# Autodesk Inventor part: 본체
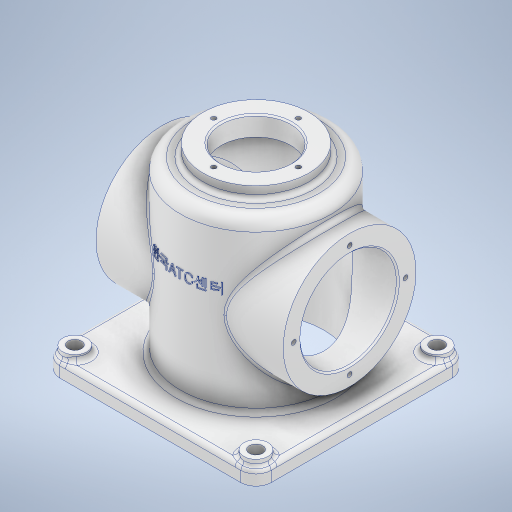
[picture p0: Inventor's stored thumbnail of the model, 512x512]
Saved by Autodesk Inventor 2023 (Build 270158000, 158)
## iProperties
Created: 2025-05
Part Number: 본체
Material: 알루미늄 6061
Document SubType Name: Modeling
Designer: ADMIN_PC
Mass: 1130.88 g
Surface Area: 1201.4 cm^2
Volume: 418.845 cm^3
Density: 2.7 g/cm^3
Appearance: 알루미늄 - 평지
Author: ADMIN_PC
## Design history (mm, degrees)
sketch "스케치1"
  geometry: L1 (-70, 70)-(70, 70); L2 (70, 70)-(70, -70); L3 (70, -70)-(-70, -70); L4 (-70, -70)-(-70, 70); L5 (-70, 70)-(70, -70); L6 (70, 70)-(-70, -70); 1 further point
  constraints: 12 end point, 2 midpoint, 2 parallel, 1 horizontal, 1 perpendicular
  dimensions: "d0" = 140 distance of L2.end L3.end; "d1" = 140 distance of L1.end L2.end
extrude "돌출1" new body sketch "스케치1" distance "d2" = 10; taper "d3" = 0 deg
sketch "스케치2"
  geometry: C1 r 50 at (0, 0); 1 further point
  constraints: 1 centre point, 1 coincident
  dimensions: "d4" = 100 diameter of C1
extrude "돌출2" join sketch "스케치2" distance "d5" = 112; taper "d6" = 0 deg
sketch "스케치3"
  geometry: C1 r 35 at (0, 0); 1 further point
  constraints: 1 centre point, 1 coincident
  dimensions: "d7" = 70 diameter of C1
extrude "돌출3" join sketch "스케치3" distance "d8" = 8; taper "d9" = 0 deg
node "작업 평면1"
sketch "스케치5"
  geometry: L1 (-26, 0)-(156, 0) reference; L2 (0, 0)-(65, 0); C1 r 44 at (65, 0)
  constraints: 2 end point, 1 centre point, 1 coincident, 1 midpoint
  dimensions: "d11" = 65 distance of L2.start L2.end; "d12" = 88 diameter of C1
extrude "돌출4" join sketch "스케치5" stored distance "d13" = 8; taper "d14" = 0 deg
sketch "스케치6" dims "d15" = 74
  geometry: L1 (0, -91)-(0, 91) reference; C1 r 44 at (0, 0) reference; 3 further points
  constraints: 1 coincident, 1 point on line, 1 vertical alignment, 2 other
hole "구멍1" sketch "스케치6" at (0, 37) diameter "d16" = 3.242; stored, may be unused: countersink angle "d20" = 90 deg, drill point angle "d22" = 118 deg; dims "d17" = 8, "d18" = 4, "d19" = 2, "d21" = 10
sketch "스케치7"
  geometry: C1 r 44 at (0, 0) reference; C2 r 32 at (0, 0); 1 further point
  constraints: 1 centre point, 1 coincident
  dimensions: "d26" = 64 diameter of C2
extrude "돌출5" cut sketch "스케치7" stored distance "d27" = 10; taper "d28" = 0 deg
sketch "스케치8"
  geometry: L1 (50, 10)-(50, 122) reference; L2 (-50, 10)-(-50, 122) reference; L3 (50, 122)-(-50, 122) reference; L4 (35, 130)-(-35, 130) reference; L5 (-35, 122)-(-35, 130) reference; L6 (35, 122)-(35, 130) reference; L7 (-35, 122)-(35, 122) reference; L8 (-70, 0)-(-70, 10) reference; L9 (70, 0)-(70, 10) reference; L10 (45, 10)-(45, 117); L11 (45, 0)-(45, 10); L12 (0, 117)-(0, 0); L13 (70, 0)-(-70, 0) reference; L14 (45, 0)-(0, 0); L15 (0, 117)-(45, 117)
  constraints: 10 end point, 3 perpendicular, 1 parallel
  dimensions: "d29" = 5 distance between parallel lines of L1 L10; "d30" = 117 distance of L12.start L12.end
revolve "회전1" sketch "스케치8" stored, may be unused: angle "d31" = 90 deg
sketch "스케치9" dims "d32" = 56
  geometry: L1 (0, 98)-(0, -98) reference; 3 further points
  constraints: 1 coincident, 1 point on line, 1 vertical alignment, 2 other
hole "구멍2" sketch "스케치9" at (0, 28) diameter "d33" = 3.242; stored, may be unused: countersink angle "d37" = 90 deg, drill point angle "d39" = 118 deg; dims "d34" = 8, "d35" = 4, "d36" = 2, "d38" = 10
sketch "스케치10"
  geometry: C1 r 35 at (0, 0) reference; C2 r 23 at (0, 0); 1 further point
  constraints: 1 centre point, 1 coincident
  dimensions: "d43" = 46 diameter of C2
extrude "돌출6" cut sketch "스케치10" stored distance "d44" = 10; taper "d45" = 0 deg
fillet "모깎기1" dims "d46" = 8
chamfer "모따기1" distance "d47" = 1; stored, may be unused: second distance "d48" = 2, angle "d49" = 45 deg
fillet "모깎기2" dims "d50" = 3
fillet "모깎기3" dims "d51" = 10
sketch "스케치11"
  geometry: C1 r 8 at (-60, 60); C2 r 8 at (60, 60); C3 r 8 at (60, -60); C4 r 8 at (-60, -60); A1 r 10 centre (-60, 60) between (-60, 70) and (-70, 60) reference; A2 r 10 centre (60, 60) between (70, 60) and (60, 70) reference; A3 r 10 centre (60, -60) between (60, -70) and (70, -60) reference; A4 r 10 centre (-60, -60) between (-70, -60) and (-60, -70) reference; 1 further point
  constraints: 4 centre point, 4 coincident
  dimensions: "d52" = 16 diameter of C1; "d53" = 16 diameter of C2; "d54" = 16 diameter of C3; "d55" = 16 diameter of C4
extrude "돌출7" join sketch "스케치11" distance "d56" = 4; taper "d57" = 0 deg
sketch "스케치12"
  geometry: C1 r 8 at (0, 0) reference; C2 r 4.5 at (0, 0); C3 r 8 at (120, 0) reference; C4 r 4.5 at (120, 0); C5 r 8 at (120, 120) reference; C6 r 4.5 at (120, 120); C7 r 8 at (0, 120) reference; C8 r 4.5 at (0, 120); 1 further point
  constraints: 4 centre point, 4 coincident
  dimensions: "d60" = 9 diameter of C2; "d61" = 9 diameter of C4; "d62" = 9 diameter of C6; "d63" = 9 diameter of C8
extrude "돌출8" cut sketch "스케치12" extent not by distance; stored distance "d64" = 0; taper "d65" = 0 deg
node "작업 평면2"
sketch "스케치13" dims "d11" = 65, "d12" = 88
  geometry: L1 (-60, 0)-(60, 0) reference; 2 further points
  constraints: 1 other
  dimensions: "d67" = 80 distance from line of L1 point (0, 80)
feature "엠보싱1" sketch "스케치13" dims "d0" = 140, "d1" = 140, "d11" = 65, "d68" = 0.5, "d69" = 0
fillet "모깎기6" dims "d70" = 3
fillet "모깎기7" dims "d71" = 3
fillet "모깎기9" dims "d76" = 3
feature "Ї耀Љ耀Ћ耀Ѝ耀Џ耀Б耀Г耀Е耀" dims "d0" = 140, "d1" = 140, "d2" = 10, "d3" = 0, "d4" = 100, "d5" = 112, "d6" = 0, "d7" = 70, "d8" = 8, "d9" = 0, "d10" = 62, "d11" = 65, "d12" = 88, "d13" = 8, "d14" = 0, "d15" = 74, "d16" = 3.242, "d17" = 8, "d18" = 4, "d19" = 2, "d20" = 90 deg, "d21" = 10, "d22" = 118 deg, "d23" = 40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
node "솔리드1"
mirror "미러1"
pattern_circular "원형 패턴1" dims angle "d24" = 360 deg
mirror "미러2"
pattern_circular "원형 패턴2" dims angle "d41" = 360 deg
feature "A9D066F2-1C7D-4E18-AEED-F7BC21143FA4" dims "d16" = 3.242, "d17" = 8, "d18" = 4, "d19" = 2, "d20" = 90 deg, "d21" = 10, "d22" = 118 deg
